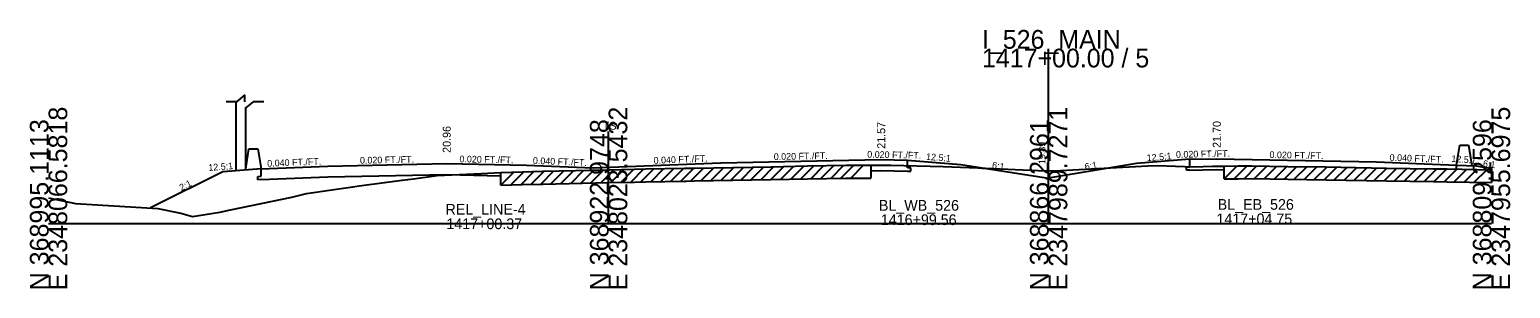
# Model space of a CAD drawing. Extents: x -170 to 2527928, y -10 to 1619750.
# Drawn here: x 2997.2 to 3219.3, y 9490.3 to 9529 of the extents above; entities that cross this region are included whole.
import ezdxf

# ---------------------------------------------------------------- set-up
doc = ezdxf.new("R2010")
doc.units = 0
for name, color, linetype in [('Default', 7, 'Continuous'), ('RD_GPK_XS_Cell', 7, 'Continuous'), ('RD_PD_NOISE-WALL-GM', 7, 'Continuous'), ('RD_XS_Base', 7, 'Continuous'), ('RD_XS_EarthShd', 7, 'Continuous'), ('RD_XS_ExGround', 7, 'Continuous'), ('RD_XS_ExPaveRet', 7, 'Continuous'), ('RD_XS_MatchLine', 7, 'Continuous'), ('RD_XS_Pave', 7, 'Continuous'), ('RD_XS_PaveShd', 7, 'Continuous'), ('RD_XS_TieSlope', 7, 'Continuous'), ('RD_XS_TX_Elev_EX', 7, 'Continuous'), ('RD_XS_TX_Slope', 7, 'Continuous'), ('RD_XS_TX_Station', 7, 'Continuous')]:
    doc.layers.add(name, color=color, linetype=linetype)

msp = doc.modelspace()

# ---------------------------------------------------------------- linework, layer by layer
at = {"layer": 'Default'}
for p, q in [((3029.46, 9519.25), (3028.21, 9518.22)), ((3029.46, 9518.22), (3029.46, 9519.25)), ((3028.21, 9518.22), (3026.62, 9518.22)), ((3030.71, 9518.22), (3029.46, 9517.19)), ((3032.3, 9518.22), (3030.71, 9518.22))]:
    msp.add_line(p, q, dxfattribs=at)
at = {"layer": 'RD_GPK_XS_Cell'}
for p, q in [((3150, 9500), (3150, 9526.16)), ((3000, 9500), (3084, 9500)), ((3084, 9500), (3150, 9500)), ((3150, 9500), (3216.42, 9500))]:
    msp.add_line(p, q, dxfattribs=at)
at = {"layer": 'RD_PD_NOISE-WALL-GM'}
for p, q in [((3028.08, 9518.22), (3028.08, 9507.9)), ((3029.58, 9508.02), (3029.58, 9517.29)), ((3029.58, 9508.2), (3030.06, 9511.2)), ((3030.06, 9511.2), (3031.4, 9511.2)), ((3031.4, 9511.2), (3031.88, 9508.2)), ((3211.17, 9508.74), (3211.65, 9511.74)), ((3211.65, 9511.74), (3212.99, 9511.74)), ((3212.99, 9511.74), (3213.48, 9508.65))]:
    msp.add_line(p, q, dxfattribs=at)
at = {"layer": 'RD_XS_Base'}
for p, q in [((3031.88, 9507.07), (3031.88, 9508.2)), ((3128.83, 9508.35), (3128.83, 9509.49)), ((3129.33, 9508.34), (3128.83, 9508.35)), ((3129.33, 9507.84), (3129.33, 9508.34)), ((3170.67, 9508.48), (3171.17, 9508.49)), ((3170.67, 9507.98), (3170.67, 9508.48)), ((3171.17, 9508.49), (3171.17, 9509.62)), ((3171.17, 9507.99), (3175.17, 9508.07)), ((3175.17, 9508.07), (3176.34, 9508.04)), ((3211.17, 9508.14), (3211.17, 9508.74)), ((3031.38, 9507.05), (3031.88, 9507.07)), ((3031.38, 9506.55), (3031.38, 9507.05)), ((3031.88, 9506.57), (3031.38, 9506.55)), ((3031.88, 9506.57), (3041.88, 9506.97)), ((3041.88, 9506.97), (3059.67, 9507.32)), ((3059.67, 9507.32), (3067.83, 9507.16)), ((3123.34, 9507.9), (3124.83, 9507.93)), ((3124.83, 9507.93), (3128.83, 9507.85)), ((3128.83, 9507.85), (3129.33, 9507.84)), ((3171.17, 9507.99), (3170.67, 9507.98))]:
    msp.add_line(p, q, dxfattribs=at)
at = {"layer": 'RD_XS_EarthShd'}
for p, q in [((3031.88, 9508.2), (3026.12, 9507.74)), ((3128.83, 9509.49), (3136.83, 9508.85)), ((3171.17, 9509.62), (3163.17, 9508.98)), ((3211.17, 9508.74), (3214.13, 9508.63)), ((3216.42, 9508.24), (3216.42, 9508.03)), ((3026.12, 9507.74), (3015.31, 9502.34))]:
    msp.add_line(p, q, dxfattribs=at)
at = {"layer": 'RD_XS_ExGround'}
msp.add_lwpolyline([(3000, 9503.86), (3004.06, 9503.02), (3016.41, 9502.27), (3019.84, 9501.54), (3021.6, 9501.05), (3025.7, 9501.68), (3027.31, 9502.07), (3036.47, 9503.96), (3038.71, 9504.5), (3042.86, 9505.1), (3045.62, 9505.5), (3046.57, 9505.62), (3053.05, 9506.5), (3054.72, 9506.71), (3058.3, 9507.21), (3064.89, 9507.49), (3067.83, 9507.65), (3071.03, 9507.74), (3074.12, 9507.83), (3084, 9508.04), (3087.9, 9508.13), (3089.55, 9508.16), (3095.38, 9508.27), (3095.69, 9508.27), (3096.88, 9508.3), (3108.37, 9508.5), (3113.81, 9508.61), (3119.57, 9508.72), (3121.51, 9508.71), (3123.34, 9508.71), (3126.35, 9508.72), (3134.2, 9508.53), (3139.37, 9508.33), (3139.97, 9508.3), (3140.13, 9508.3), (3140.51, 9508.28), (3144.97, 9508.08), (3149.58, 9507.87), (3150, 9507.89), (3151.78, 9507.95), (3164.86, 9508.65), (3166.26, 9508.69), (3171.76, 9508.5), (3174.58, 9508.56), (3176.34, 9508.6), (3178.43, 9508.62), (3180.41, 9508.64), (3185.9, 9508.55), (3191.64, 9508.46), (3200.67, 9508.3), (3204.2, 9508.24), (3207.74, 9508.19), (3209.79, 9508.16), (3216.42, 9508.03)], dxfattribs=at)
at = {"layer": 'RD_XS_ExPaveRet'}
for p, q in [((3081.33, 9506.07), (3083.29, 9508.03)), ((3082.83, 9506.1), (3084.79, 9508.06)), ((3084.33, 9506.13), (3086.29, 9508.09)), ((3085.83, 9506.16), (3087.79, 9508.12)), ((3087.33, 9506.2), (3089.29, 9508.16)), ((3088.83, 9506.23), (3090.79, 9508.19)), ((3090.33, 9506.26), (3092.29, 9508.21)), ((3091.83, 9506.29), (3093.79, 9508.24)), ((3093.33, 9506.32), (3095.29, 9508.27)), ((3094.83, 9506.34), (3096.79, 9508.3)), ((3096.33, 9506.37), (3098.29, 9508.32)), ((3097.83, 9506.4), (3099.78, 9508.35)), ((3099.33, 9506.42), (3101.28, 9508.38)), ((3100.83, 9506.45), (3102.78, 9508.4)), ((3102.33, 9506.48), (3104.28, 9508.43)), ((3103.83, 9506.5), (3105.78, 9508.46)), ((3105.33, 9506.53), (3107.28, 9508.48)), ((3106.83, 9506.56), (3108.79, 9508.51)), ((3108.33, 9506.59), (3110.29, 9508.54)), ((3109.83, 9506.62), (3111.79, 9508.57)), ((3111.33, 9506.65), (3113.29, 9508.6)), ((3112.83, 9506.68), (3114.79, 9508.63)), ((3114.33, 9506.71), (3116.29, 9508.66)), ((3115.83, 9506.73), (3117.79, 9508.69)), ((3117.33, 9506.76), (3119.29, 9508.71)), ((3118.83, 9506.79), (3120.76, 9508.72)), ((3120.33, 9506.8), (3122.25, 9508.71)), ((3123.34, 9508.71), (3123.34, 9506.79)), ((3176.34, 9506.69), (3178.27, 9508.62)), ((3176.34, 9506.69), (3176.34, 9508.6)), ((3177.84, 9506.7), (3179.77, 9508.63)), ((3179.34, 9506.71), (3181.25, 9508.62)), ((3180.84, 9506.71), (3182.73, 9508.6)), ((3182.34, 9506.69), (3184.23, 9508.57)), ((3183.84, 9506.66), (3185.73, 9508.55)), ((3185.34, 9506.64), (3187.23, 9508.53)), ((3186.84, 9506.62), (3188.73, 9508.5)), ((3188.34, 9506.59), (3190.23, 9508.48)), ((3189.84, 9506.57), (3191.73, 9508.45)), ((3191.34, 9506.54), (3193.23, 9508.43)), ((3192.84, 9506.52), (3194.73, 9508.4)), ((3194.34, 9506.49), (3196.23, 9508.38)), ((3195.84, 9506.47), (3197.73, 9508.35)), ((3197.34, 9506.44), (3199.23, 9508.33)), ((3198.84, 9506.42), (3200.73, 9508.3)), ((3200.34, 9506.39), (3202.22, 9508.27)), ((3201.84, 9506.36), (3203.72, 9508.25)), ((3203.34, 9506.34), (3205.23, 9508.22)), ((3204.84, 9506.31), (3206.73, 9508.2)), ((3206.34, 9506.29), (3208.23, 9508.18)), ((3207.84, 9506.27), (3209.73, 9508.16)), ((3209.34, 9506.25), (3211.22, 9508.13)), ((3210.84, 9506.23), (3212.72, 9508.11)), ((3212.34, 9506.2), (3214.22, 9508.08)), ((3213.84, 9506.17), (3215.72, 9508.05)), ((3216.42, 9508.03), (3216.42, 9506.12)), ((3067.83, 9505.73), (3069.8, 9507.7)), ((3067.83, 9505.73), (3067.83, 9507.65)), ((3067.83, 9505.73), (3071.03, 9505.82)), ((3069.33, 9505.77), (3071.3, 9507.74)), ((3070.83, 9505.81), (3072.81, 9507.79)), ((3071.03, 9505.82), (3074.12, 9505.91)), ((3072.33, 9505.86), (3074.31, 9507.83)), ((3073.83, 9505.9), (3075.79, 9507.86)), ((3074.12, 9505.91), (3084, 9506.12)), ((3075.33, 9505.94), (3077.29, 9507.89)), ((3076.83, 9505.97), (3078.79, 9507.93)), ((3078.33, 9506), (3080.29, 9507.96)), ((3079.83, 9506.03), (3081.79, 9507.99)), ((3084, 9506.12), (3087.9, 9506.21)), ((3087.9, 9506.21), (3089.55, 9506.25)), ((3089.55, 9506.25), (3095.38, 9506.35)), ((3095.38, 9506.35), (3095.69, 9506.36)), ((3095.69, 9506.36), (3096.88, 9506.38)), ((3096.88, 9506.38), (3108.37, 9506.59)), ((3108.37, 9506.59), (3113.81, 9506.7)), ((3113.81, 9506.7), (3119.57, 9506.8)), ((3119.57, 9506.8), (3121.51, 9506.8)), ((3121.51, 9506.8), (3123.34, 9506.79)), ((3176.34, 9506.69), (3178.43, 9506.7)), ((3178.43, 9506.7), (3180.41, 9506.72)), ((3180.41, 9506.72), (3185.9, 9506.63)), ((3185.9, 9506.63), (3191.64, 9506.54)), ((3191.64, 9506.54), (3200.67, 9506.38)), ((3200.67, 9506.38), (3204.2, 9506.32)), ((3204.2, 9506.32), (3207.74, 9506.27)), ((3207.74, 9506.27), (3209.79, 9506.25)), ((3209.79, 9506.25), (3216.42, 9506.12))]:
    msp.add_line(p, q, dxfattribs=at)
at = {"layer": 'RD_XS_MatchLine'}
msp.add_line((3084, 9500), (3084, 9513.78), dxfattribs=at)
at = {"layer": 'RD_XS_Pave'}
for p, q in [((3041.88, 9508.6), (3059.67, 9508.96)), ((3059.67, 9508.96), (3071.67, 9508.72)), ((3100.83, 9509.09), (3124.83, 9509.57)), ((3175.17, 9509.7), (3199.17, 9509.22))]:
    msp.add_line(p, q, dxfattribs=at)
at = {"layer": 'RD_XS_PaveShd'}
for p, q in [((3031.88, 9508.2), (3041.88, 9508.6)), ((3071.67, 9508.72), (3081.66, 9508.32)), ((3081.66, 9508.32), (3100.83, 9509.09)), ((3124.83, 9509.57), (3128.83, 9509.49)), ((3171.17, 9509.62), (3175.17, 9509.7)), ((3199.17, 9509.22), (3211.17, 9508.74))]:
    msp.add_line(p, q, dxfattribs=at)
at = {"layer": 'RD_XS_TieSlope'}
for p, q in [((3136.83, 9508.85), (3150, 9506.79)), ((3163.17, 9508.98), (3150, 9506.79)), ((3214.13, 9508.63), (3216.42, 9508.25))]:
    msp.add_line(p, q, dxfattribs=at)

# ---------------------------------------------------------------- texts
at = {"layer": 'RD_GPK_XS_Cell'}
for s, p in [('I_526_MAIN', (3140, 9526.16)), ('1417+00.00 / 5', (3140, 9523.36))]:
    msp.add_text(s, height=2.8, dxfattribs=at).set_placement(p)
for s, p in [('E 2348066.5818', (3002.8, 9490)), ('E 2348023.5432', (3086.8, 9490)), ('E 2347989.7271', (3152.8, 9490)), ('E 2347955.6975', (3219.22, 9490)), ('N 368995.1113', (3000, 9490)), ('N 368922.9748', (3084, 9490)), ('N 368866.2961', (3150, 9490)), ('N 368809.2596', (3216.42, 9490))]:
    msp.add_text(s, height=2.8, rotation=90, dxfattribs=at).set_placement(p)
at = {"layer": 'RD_XS_MatchLine'}
msp.add_text('TS', height=1.2, dxfattribs=at).set_placement((3083.14, 9514.03))
at = {"layer": 'RD_XS_TX_Elev_EX'}
msp.add_text('19.89', height=1, rotation=90, dxfattribs=at).set_placement((3149.5, 9508.89))
at = {"layer": 'RD_XS_TX_Slope'}
for s, rotation, p in [('0.020 FT./FT.', 1.1458, (3108.78, 9509.5)), ('0.020 FT./FT.', 358.8542, (3122.79, 9509.86)), ('12.5:1', 355.4261, (3131.59, 9509.53)), ('12.5:1', 4.5739, (3164.75, 9509.32)), ('0.020 FT./FT.', 1.1458, (3169.11, 9509.83)), ('0.020 FT./FT.', 358.8542, (3183.12, 9509.8)), ('0.040 FT./FT.', 357.7094, (3201.13, 9509.4)), ('12.5:1', 4.5739, (3024.01, 9507.86)), ('0.040 FT./FT.', 2.2906, (3032.82, 9508.49)), ('0.020 FT./FT.', 1.1458, (3046.72, 9508.95)), ('0.020 FT./FT.', 358.8542, (3061.62, 9509.17)), ('0.040 FT./FT.', 357.7094, (3072.63, 9508.93)), ('0.040 FT./FT.', 2.2906, (3090.77, 9508.93)), ('6:1', 350.5377, (3141.45, 9508.28)), ('6:1', 9.4623, (3155.5, 9507.99)), ('12.5:1', 355.4261, (3210.38, 9509.24)), ('6:1', 352.6182, (3215.1, 9508.51)), ('2:1', 26.5651, (3019.92, 9504.85))]:
    msp.add_text(s, height=1, rotation=rotation, dxfattribs=at).set_placement(p)
at = {"layer": 'RD_XS_TX_Station'}
for s, p in [(' 21.57', (3125.49, 9510.74)), (' 21.70', (3175.82, 9510.88)), (' 20.96', (3060.32, 9510.13))]:
    msp.add_text(s, height=1.2, rotation=90, dxfattribs=at).set_placement(p)
for s, p in [('BL_EB_526', (3175.36, 9502.06)), ('REL_LINE-4', (3059.54, 9501.33)), ('BL_WB_526', (3124.54, 9501.92)), ('1416+99.56', (3124.83, 9499.77)), ('1417+04.75', (3175.17, 9499.9)), ('1417+00.37', (3059.67, 9499.16))]:
    msp.add_text(s, height=1.6, dxfattribs=at).set_placement(p)

doc.saveas('drawing.dxf')
